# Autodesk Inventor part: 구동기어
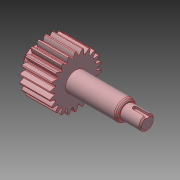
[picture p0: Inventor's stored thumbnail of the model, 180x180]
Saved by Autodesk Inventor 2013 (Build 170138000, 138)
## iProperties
Created: 2024-02
Part Number: 구동기어
Material: 강철, 탄소
Document SubType Name: Modeling
Designer: mdu-01
Density: 1 g/cm^3
Author: mdu-01
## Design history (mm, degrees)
sketch "스케치1"
  geometry: L1 (0, 0)-(80, 0); L2 (80, 0)-(80, 4); L3 (79, 5)-(66, 5); L4 (66, 5)-(66, 5.423); L5 (63.732, 7)-(30, 7); L6 (30, 7)-(30, 14.625); L7 (30, 14.625)-(9, 14.625); L8 (9, 14.625)-(9, 7); L9 (9, 7)-(1, 7); L10 (0, 6)-(0, 0); L11 (9, 16.5)-(30, 16.5); L12 (80, 4)-(79, 5); L13 (1, 7)-(0, 6); L14 (65.5, 6.289)-(64.732, 6.732); L15 (70, 5)-(70, 3.2); L16 (70, 3.2)-(80, 3.2); A1 r 2 centre (63.732, 5) between (64.732, 6.732) and (63.732, 7); A2 r 1 centre (65, 5.423) between (66, 5.423) and (65.5, 6.289); 3 further points
  constraints: 32 end point, 10 point on line, 8 parallel, 4 perpendicular, 4 point on circle, 4 tangent, 2 centre point, 1 collinear, 1 horizontal
  dimensions: "d0" = 14 diameter of L9 L1; "d2" = 9 distance between parallel lines of L8 L10; "d3" = 21 distance between parallel lines of L6 L8; "d4" = 33 diameter of L11 L1; "d5" = 1.875 distance between parallel lines of L7 L11; "d6" = 14 distance between parallel lines of L2 L4; "d7" = 50 distance between parallel lines of L6 L2; "d8" = 10 diameter of L3 L1; "d9" = 1 distance of L2.end point (80, 5); "d10" = 1 distance of L3.start point (80, 5) (= d9); "d11" = 1 distance of L9.end point (0, 7) (= d9); "d12" = 1 distance of L10.start point (0, 7) (= d11); "d13" = 12 diameter of point (66, 6) L1; "d14" = 30 deg angle of L5 L14; "d15" = 2 radius of A1; "d16" = 1 radius of A2; "d17" = 1.8 distance between parallel lines of L16 L3; "d18" = 10 distance between parallel lines of L15 L2
revolve "회전1" stored, may be unused: angle "d19" = 90 deg
extrude "돌출1" cut sketch "스케치1" stored distance "d20" = 3; taper "d21" = 0 deg
fillet "모깎기1"
sketch "스케치2" dims "d22" = 33
  geometry: L1 (0, 0)-(0, 18); A1 r 18 centre (0, 0) between (0.428, 17.995) and (-0.428, 17.995); A2 r 7.045 centre (-5.482, 14.16) between (1.553, 14.542) and (0.428, 17.995); A3 r 7.045 centre (5.482, 14.16) between (-0.428, 17.995) and (-1.553, 14.542); A4 r 14.625 centre (0, 0) between (1.553, 14.542) and (-1.553, 14.542); 3 further points
  constraints: 10 point on circle, 4 centre point, 3 symmetric about line, 2 coincident, 2 end point, 1 vertical, 8 other
  dimensions: "d23" = 1.5 dimension on A1; "d24" = 1.1775 horizontal distance of point (1.178, 16.458) point (0, 0); "d25" = 0.75 horizontal distance of A1.start point (1.178, 16.458); "d26" = 0.375 horizontal distance of A2.start point (1.178, 16.458)
extrude "돌출2" join sketch "스케치2" stored distance "d27" = 3; taper "d28" = 0 deg
fillet "모깎기2" dims "d32" = 0.375
node "솔리드1"
pattern_circular "원형 패턴1" dims angle "d34" = 360 deg
